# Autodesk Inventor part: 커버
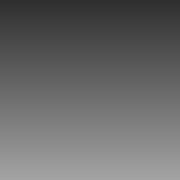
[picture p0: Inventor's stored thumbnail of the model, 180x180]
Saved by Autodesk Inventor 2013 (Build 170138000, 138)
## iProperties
Created: 2015-07
Part Number: 커버
Material: 일반
Document SubType Name: Modeling
Designer: user
Density: 1 g/cm^3
Author: user
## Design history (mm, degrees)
